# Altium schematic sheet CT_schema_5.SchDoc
size 279 x 144 mm
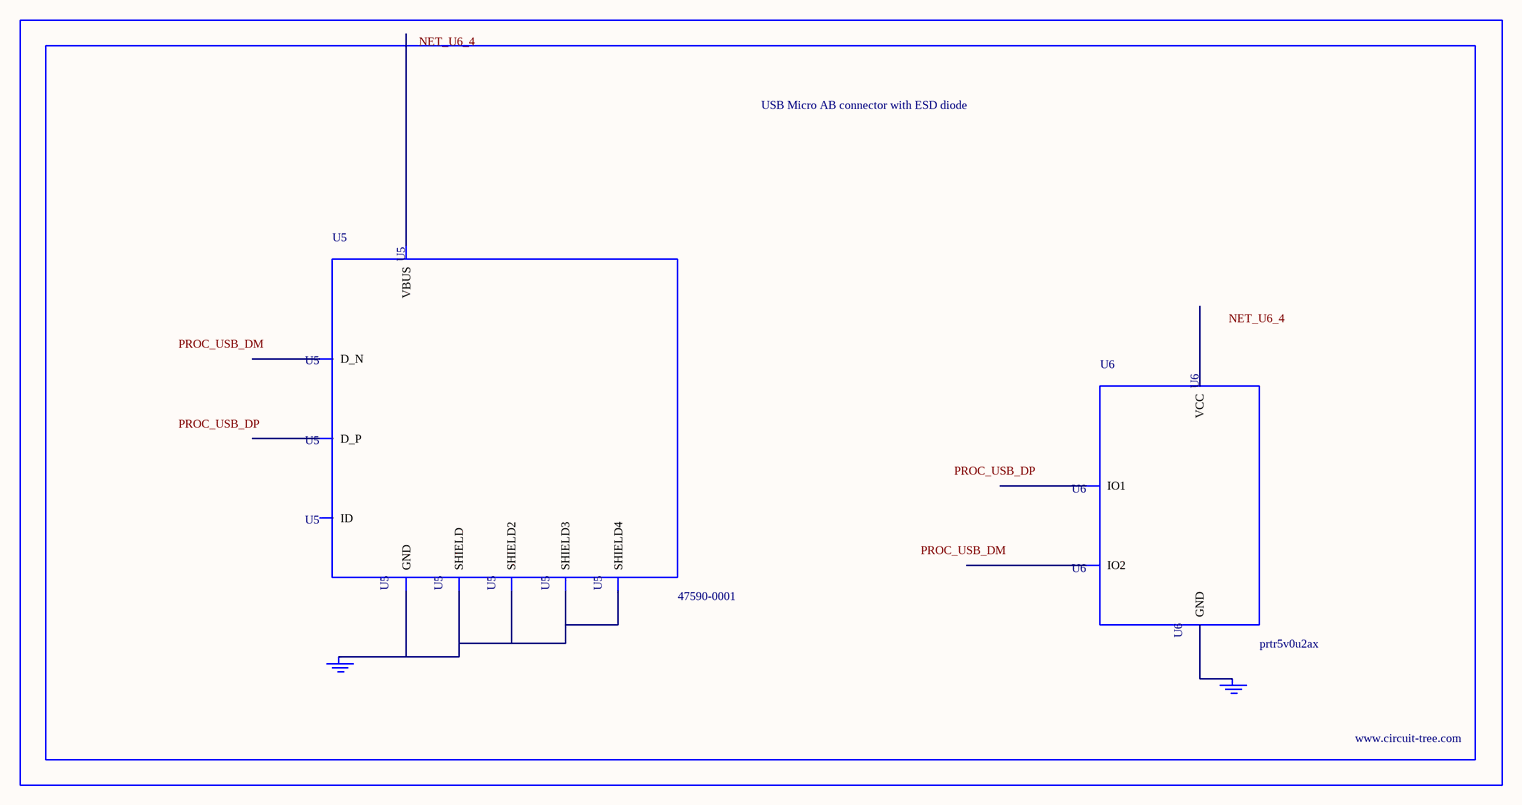
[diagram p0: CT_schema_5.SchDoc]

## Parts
BORDER4  (no value)
GND_INSTANCE_4_0  (no value)
GND_INSTANCE_4_1  (no value)
U5  47590-0001  [MICRO_USB_AB]
U6  prtr5v0u2ax  [SOT143B]

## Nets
NetGND_INSTANCE_4_0_0: GND_INSTANCE_4_0.0(GND) U5.5(GND) U5.6(SHIELD) U5.7(SHIELD2) U5.8(SHIELD3) U5.9(SHIELD4)
NetGND_INSTANCE_4_1_0: GND_INSTANCE_4_1.0(GND) U6.1(GND)

Not connected (* = marked no-connect by the designer): U5 1(VBUS) 2(D_N) 3(D_P) 4(ID); U6 2(IO1) 3(IO2) 4(VCC)

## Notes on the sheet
- Labels drawn without touching a wire or pin: NET_U6_4, PROC_USB_DM, PROC_USB_DP

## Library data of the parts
BORDER4 = BORDER_PAGE4
GND_INSTANCE_4_0 GND_INSTANCE_4_1 = GND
